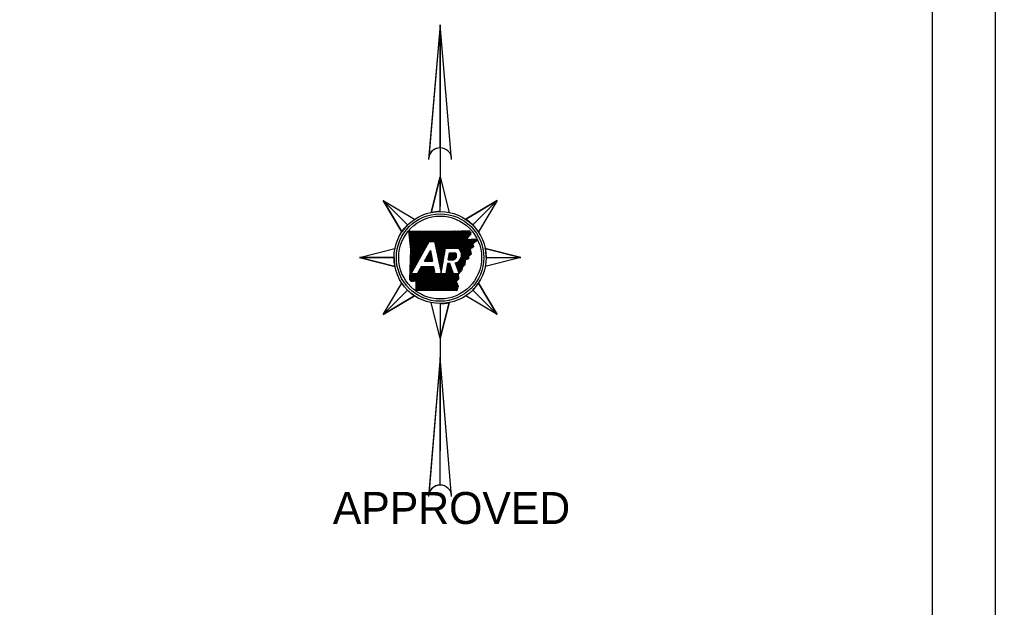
# Model space of a CAD drawing. Extents: x -819161 to 80911, y -6604 to 768454.
# Drawn here: x 48407 to 52278, y 2641 to 4974 of the extents above; entities that cross this region are included whole.
import ezdxf

# ---------------------------------------------------------------- set-up
doc = ezdxf.new("R2010")
doc.units = 0
for name, color, linetype in [('29', 7, 'Continuous'), ('Default', 7, 'Continuous'), ('DSN_DRFT_Common-Annotations', 7, 'Continuous'), ('DSN_DRFT_Junk-No-Plot', 7, 'Continuous'), ('SHET_Border-Lines', 7, 'Continuous')]:
    doc.layers.add(name, color=color, linetype=linetype)

msp = doc.modelspace()

# ---------------------------------------------------------------- linework, layer by layer
at = {"layer": 'Default'}
msp.add_lwpolyline([(35278.1, 10659.9), (35278.1, -340.1), (52278.1, -340.1), (52278.1, 10659.9)], close=True, dxfattribs=at)
at = {"layer": 'DSN_DRFT_Common-Annotations'}
for p, q in [((50075.3, 4953.1), (50030.3, 4426.6)), ((50075.3, 4953.1), (50075.3, 4232)), ((50075.3, 4464.5), (50075.3, 4953.1)), ((50030.9, 4434), (50032.9, 4436)), ((50031.1, 4436.8), (50035.3, 4440.9)), ((50075.3, 4349.1), (50039.7, 4208.6)), ((50075.3, 4212.1), (50075.3, 4349.1)), ((49849.2, 4255.5), (49946.1, 4158.6)), ((49946.1, 4158.6), (49849.2, 4255.5)), ((49849.2, 4255.5), (49923.4, 4131)), ((50301.3, 4255.5), (50176.8, 4181.3)), ((50204.4, 4158.6), (50301.3, 4255.5)), ((50204.4, 4158.6), (50301.3, 4255.5)), ((49950.8, 4132.4), (49952.4, 4134)), ((49951.3, 4127.8), (49957.5, 4134)), ((49951.9, 4123.2), (49962.7, 4134)), ((49952.5, 4118.6), (49967.9, 4134)), ((49953.1, 4114), (49973, 4134)), ((49953.6, 4109.4), (49978.2, 4134)), ((49954.2, 4104.8), (49983.4, 4134)), ((49954.8, 4100.2), (49988.5, 4134)), ((49955.3, 4095.6), (49993.7, 4134)), ((49955.9, 4091.1), (49998.8, 4134)), ((49956.5, 4086.5), (50004, 4134)), ((49957.1, 4081.9), (50009.2, 4134)), ((49957.6, 4077.3), (50014.3, 4134)), ((49958.2, 4072.7), (50019.5, 4134)), ((49958.4, 4021.2), (50071.3, 4134.1)), ((49958.6, 4026.5), (50066.1, 4134.1)), ((49958.7, 4031.9), (50060.9, 4134)), ((49958.8, 4068.1), (50024.7, 4134)), ((49958.9, 4037.2), (50055.7, 4134)), ((49959.1, 4042.6), (50050.5, 4134)), ((49959.3, 4047.9), (50045.4, 4134)), ((49959.3, 4063.5), (50029.8, 4134)), ((49959.4, 4053.2), (50040.2, 4134)), ((49959.6, 4058.6), (50035, 4134)), ((50035.1, 4092.7), (50076.4, 4134.1)), ((50040.3, 4092.7), (50081.6, 4134.1)), ((50045.4, 4092.7), (50086.8, 4134.1)), ((50050.6, 4092.7), (50092.1, 4134.2)), ((50053.8, 4090.8), (50097.3, 4134.3)), ((50054.7, 4086.5), (50102.6, 4134.4)), ((50055.6, 4082.3), (50107.8, 4134.5)), ((50056.5, 4078), (50113.1, 4134.5)), ((50057.5, 4073.8), (50118.3, 4134.6)), ((50058.4, 4069.5), (50123.6, 4134.7)), ((50059.3, 4065.3), (50128.8, 4134.8)), ((50060.2, 4061), (50134.1, 4134.9)), ((50061.1, 4056.7), (50139.3, 4135)), ((50062, 4052.5), (50144.5, 4135)), ((50062.9, 4048.2), (50149.8, 4135.1)), ((50063.8, 4044), (50155, 4135.2)), ((50064.7, 4039.7), (50160.3, 4135.3)), ((50065.6, 4035.5), (50165.6, 4135.4)), ((50101.5, 4066.2), (50170.9, 4135.5)), ((50106.7, 4066.2), (50176.2, 4135.7)), ((50111.9, 4066.2), (50181.5, 4135.8)), ((50117, 4066.2), (50186.7, 4135.9)), ((50122.2, 4066.2), (50192, 4136)), ((50127.4, 4066.2), (50193.2, 4132)), ((50132.5, 4066.2), (50195.7, 4129.3)), ((50137.7, 4066.2), (50196.4, 4124.8)), ((50142.9, 4066.2), (50184.6, 4107.9)), ((49958, 4010.5), (50021.2, 4073.6)), ((49958.2, 4015.8), (50027.9, 4085.6)), ((49959.9, 3965.5), (50032, 4092.7)), ((50032, 4092.7), (50053.4, 4092.7)), ((50096.9, 4066.2), (50146.9, 4066.2)), ((50147.6, 4065.7), (50183.5, 4101.7)), ((50150.4, 4063.4), (50189, 4102)), ((50152.9, 4060.7), (50194.4, 4102.3)), ((50155.1, 4057.8), (50199.9, 4102.5)), ((50157, 4054.5), (50205.3, 4102.8)), ((50158.6, 4051), (50210.8, 4103.1)), ((50159.5, 4031.1), (50206.4, 4078)), ((50159.8, 4047), (50215.7, 4102.8)), ((50160.5, 4042.5), (50218.1, 4100.1)), ((50160.5, 4037.4), (50205.8, 4082.6)), ((50200.6, 4067.1), (50206.9, 4073.4)), ((50215.8, 4092.6), (50220.5, 4097.3)), ((50394.9, 4029.5), (50254.4, 4065)), ((49755.6, 4029.5), (49892.6, 4029.5)), ((49892.6, 4029.5), (49755.6, 4029.5)), ((49755.6, 4029.5), (49896.1, 3993.9)), ((49957.3, 3989.1), (49994.2, 4026)), ((49957.5, 3994.5), (50000.9, 4037.9)), ((49957.7, 3999.8), (50007.7, 4049.8)), ((49957.8, 4005.2), (50014.4, 4061.7)), ((50012.9, 4015.4), (50036.5, 4057.1)), ((50013.2, 4015.4), (50039.7, 4042)), ((50018.3, 4015.4), (50040.6, 4037.7)), ((50019.3, 4026.8), (50038.8, 4046.2)), ((50023.5, 4015.4), (50041.5, 4033.5)), ((50026.1, 4038.7), (50037.9, 4050.5)), ((50028.7, 4015.4), (50042.5, 4029.2)), ((50032.8, 4050.6), (50037, 4054.7)), ((50066.6, 4031.2), (50095.9, 4060.5)), ((50067.5, 4027), (50094.8, 4054.3)), ((50068.4, 4022.7), (50093.7, 4048)), ((50069.3, 4018.4), (50092.6, 4041.8)), ((50070.2, 4014.2), (50091.5, 4035.5)), ((50071.1, 4009.9), (50090.4, 4029.2)), ((50107.8, 4021), (50134.9, 4048.2)), ((50108.8, 4027.3), (50129.8, 4048.2)), ((50109.9, 4033.5), (50124.6, 4048.2)), ((50111, 4039.8), (50119.4, 4048.2)), ((50112.1, 4046), (50114.3, 4048.2)), ((50112.5, 4048.2), (50136, 4048.2)), ((50112.9, 4021), (50137.8, 4045.9)), ((50118.1, 4021), (50139.5, 4042.5)), ((50123.2, 4021), (50140.5, 4038.3)), ((50128.4, 4021), (50140.1, 4032.7)), ((50138.1, 3999.5), (50195.4, 4056.7)), ((50139.5, 3995.7), (50196.4, 4052.5)), ((50140.9, 3991.9), (50197.3, 4048.3)), ((50142.3, 3988.2), (50198.3, 4044.1)), ((50155, 4021.5), (50194.4, 4060.9)), ((50180.7, 4021.3), (50187.9, 4028.6)), ((50257.9, 4029.5), (50394.9, 4029.5)), ((50257.9, 4029.5), (50394.9, 4029.5)), ((49956.8, 3973.1), (49974, 3990.3)), ((49957, 3978.4), (49980.7, 4002.2)), ((49957.1, 3983.8), (49987.4, 4014.1)), ((49957.7, 3937.9), (50012, 3992.2)), ((49960.8, 3935.8), (50017.2, 3992.2)), ((49964.5, 3934.3), (50022.4, 3992.2)), ((49970.6, 3935.3), (50027.5, 3992.2)), ((49975.9, 3935.4), (50032.7, 3992.2)), ((49979.9, 3934.3), (50037.8, 3992.2)), ((49980.1, 3924.1), (50048.2, 3992.2)), ((49980.1, 3929.3), (50043, 3992.2)), ((49980.1, 3919), (50050.9, 3989.7)), ((49999.8, 3992.2), (49984.6, 3965.5)), ((49990.5, 3975.8), (50006.9, 3992.2)), ((49997.2, 3987.7), (50001.7, 3992.2)), ((50050.4, 3992.2), (49999.8, 3992.2)), ((50012.9, 4015.4), (50045.4, 4015.4)), ((50033.8, 4015.4), (50043.4, 4025)), ((50039, 4015.4), (50044.3, 4020.7)), ((50044.2, 4015.4), (50045.2, 4016.4)), ((50072, 4005.7), (50089.3, 4023)), ((50072.9, 4001.4), (50088.2, 4016.7)), ((50073.8, 3997.2), (50087.1, 4010.5)), ((50074.8, 3992.9), (50086.1, 4004.2)), ((50075.7, 3988.7), (50085, 3998)), ((50076.6, 3984.4), (50083.9, 3991.7)), ((50098.9, 3970.6), (50119.3, 3991)), ((50100, 3976.9), (50117.9, 3994.7)), ((50101.1, 3983.1), (50116.5, 3998.5)), ((50102.2, 3989.4), (50115.1, 4002.3)), ((50103.3, 3995.6), (50113.6, 4005.9)), ((50104.4, 4001.9), (50108.4, 4005.9)), ((50113.8, 4005.9), (50105.1, 4005.9)), ((50107.7, 4021), (50129.2, 4021)), ((50128.7, 3965.5), (50113.8, 4005.9)), ((50134.9, 4008.1), (50150.7, 3965.5)), ((50135.3, 4007), (50136.9, 4008.6)), ((50136.7, 4003.2), (50146.6, 4013.1)), ((50143.7, 3984.4), (50174.7, 4015.4)), ((50145.1, 3980.6), (50174.1, 4009.6)), ((50146.5, 3976.8), (50173.5, 4003.9)), ((50147.9, 3973.1), (50163.7, 3988.9)), ((49955.8, 3941.1), (49980.1, 3965.5)), ((49955.9, 3946.4), (49975, 3965.5)), ((49956.1, 3951.7), (49969.8, 3965.5)), ((49956.2, 3957.1), (49964.7, 3965.5)), ((49956.4, 3962.4), (49960.5, 3966.5)), ((49956.6, 3967.8), (49967.2, 3978.4)), ((49984.6, 3965.5), (49959.9, 3965.5)), ((49980.1, 3913.8), (50051.8, 3985.5)), ((49980.2, 3908.7), (50052.7, 3981.2)), ((49980.2, 3903.5), (50053.6, 3977)), ((49980.3, 3898.4), (50054.5, 3972.7)), ((49985.4, 3898.4), (50055.5, 3968.5)), ((49990.6, 3898.4), (50057.6, 3965.5)), ((49995.7, 3898.4), (50062.8, 3965.5)), ((50000.9, 3898.4), (50068, 3965.5)), ((50006, 3898.4), (50073.1, 3965.5)), ((50011.2, 3898.4), (50078.3, 3965.5)), ((50016.4, 3898.4), (50083.5, 3965.5)), ((50021.5, 3898.4), (50088.6, 3965.5)), ((50026.7, 3898.3), (50093.8, 3965.5)), ((50031.8, 3898.3), (50120.7, 3987.2)), ((50037, 3898.3), (50122.1, 3983.4)), ((50042.2, 3898.3), (50123.5, 3979.6)), ((50047.3, 3898.3), (50124.9, 3975.9)), ((50052.5, 3898.3), (50126.3, 3972.1)), ((50098, 3965.5), (50056.1, 3965.5)), ((50057.6, 3898.3), (50127.7, 3968.3)), ((50062.8, 3898.3), (50130, 3965.5)), ((50067.9, 3898.3), (50135.1, 3965.5)), ((50073.1, 3898.3), (50140.3, 3965.5)), ((50077.5, 3980.1), (50082.8, 3985.5)), ((50078.3, 3898.3), (50145.5, 3965.5)), ((50078.4, 3975.9), (50081.7, 3979.2)), ((50079.3, 3971.6), (50080.6, 3972.9)), ((50083.4, 3898.3), (50147.2, 3962)), ((50088.6, 3898.2), (50147.4, 3957.1)), ((50093.7, 3898.2), (50147.7, 3952.2)), ((50150.7, 3965.5), (50128.7, 3965.5)), ((50149.3, 3969.3), (50161.5, 3981.5)), ((50098.9, 3898.2), (50147.9, 3947.2)), ((50104, 3898.2), (50139.4, 3933.6)), ((50109.2, 3898.2), (50141, 3930)), ((50114.4, 3898.2), (50142.6, 3926.4)), ((50119.5, 3898.2), (50144.2, 3922.9)), ((50124.7, 3898.2), (50145.8, 3919.3)), ((50129.8, 3898.2), (50147.1, 3915.5)), ((50301.3, 3803.4), (50227.1, 3927.9)), ((49849.2, 3803.4), (49946.1, 3900.3)), ((49946.1, 3900.3), (49849.2, 3803.4)), ((49849.2, 3803.4), (49973.7, 3877.6)), ((50135, 3898.2), (50144.8, 3908)), ((50140.1, 3898.2), (50142.4, 3900.5)), ((50204.4, 3900.3), (50301.3, 3803.4)), ((50204.4, 3900.3), (50301.3, 3803.4)), ((50075.3, 3709.8), (50110.8, 3850.3)), ((50075.3, 3846.8), (50075.3, 3846.8)), ((50075.3, 3846.8), (50075.3, 3262.1)), ((50075.3, 3846.8), (50075.3, 3709.8)), ((50075.3, 3633.5), (50030.2, 3088.5)), ((50075.3, 3126.6), (50075.3, 3633.5))]:
    msp.add_line(p, q, dxfattribs=at)
for points in [[(50120.9, 4418.9), (50075.3, 4953.1), (50029.6, 4418.9)], [(50039.7, 4208.6), (50075.3, 4349.1), (50110.8, 4208.6)], [(49923.4, 4131), (49849.2, 4255.5), (49973.7, 4181.3)], [(50176.8, 4181.3), (50301.3, 4255.5), (50227.1, 4131)], [(49950.6, 4134), (50021.8, 4134), (50084.4, 4134.1), (50158.2, 4135.2), (50192.4, 4136)], [(49955.7, 3941.2), (49959.7, 4060.8), (49950.6, 4134)], [(49896.1, 3993.9), (49755.6, 4029.5), (49896.1, 4065)], [(50053.4, 4092.7), (50079.9, 3968.9), (50096.9, 4066.2)], [(50214.8, 4103.3), (50220.9, 4096.8), (50205.5, 4084.2), (50207.2, 4071.4), (50194, 4062.8), (50198.5, 4043.1), (50188.4, 4033.9), (50187.5, 4023.8), (50175.1, 4019.3), (50173.2, 4000.3), (50164.3, 3990.8), (50160, 3976.5), (50147.1, 3964.6), (50148.1, 3943.7), (50139.3, 3933.9), (50147.3, 3916), (50141.7, 3898.2)], [(50181.8, 4101.6), (50215.2, 4103.3)], [(50254.4, 4065), (50394.9, 4029.5), (50254.4, 3993.9)], [(50036.5, 4057.1), (50045.4, 4015.4)], [(50107.7, 4021), (50112.5, 4048.2)], [(50056.1, 3965.5), (50050.4, 3992.2)], [(50105.1, 4005.9), (50098, 3965.5)], [(49973.7, 3877.6), (49849.2, 3803.4), (49923.4, 3927.9)], [(50141.7, 3898.2), (49980.2, 3898.4), (49980.1, 3934.1)], [(50227.1, 3927.9), (50301.3, 3803.4), (50176.8, 3877.6)], [(50110.8, 3850.3), (50075.3, 3709.8), (50039.7, 3850.3)], [(50120.9, 3081), (50075.3, 3633.5), (50029.6, 3081)]]:
    msp.add_lwpolyline(points, dxfattribs=at)
for radius in [182.6, 173.5, 164.4]:
    msp.add_circle((50075.3, 4029.5), radius, dxfattribs=at)
for centre, radius, start, end in [((50075.3, 4418.9), 45.7, 0, 180), ((50075.3, 4418.9), 45.7, 90, 170.2296), ((50075.3, 4029.5), 182.6, 90, 101.2291), ((50075.3, 4029.5), 182.6, 45, 56.2291), ((50075.3, 4029.5), 182.6, 135, 146.2291), ((50128.3, 4039.7), 32.3, 281.8626, 54.8705), ((50075.3, 4029.5), 182.6, 0, 11.2291), ((50075.3, 4029.5), 182.6, 180, 191.2291), ((50124, 4036.8), 16.5, 288.1268, 43.8902), ((50075.3, 4029.5), 182.6, 315, 326.2291), ((50075.3, 4029.5), 182.6, 225, 236.2291), ((50075.3, 4029.5), 182.6, 270, 281.2291), ((50075.3, 3081), 45.7, 0, 180), ((50075.3, 3081), 45.7, 90, 170.5511)]:
    msp.add_arc(centre, radius, start, end, dxfattribs=at)
for points in [[(50192.4, 4136), (50192.6, 4134.1), (50193.2, 4133.1), (50193.3, 4131.2), (50194, 4130.4), (50195.3, 4129.6), (50196.5, 4128.4), (50196.7, 4126.9), (50196.4, 4125.3), (50196.3, 4123.6), (50196.1, 4122.1), (50195.9, 4120.7), (50194.8, 4119.6), (50193.8, 4118.8), (50192.9, 4117.9), (50192.2, 4117), (50191, 4115.9), (50189.9, 4114.8), (50189, 4113.8), (50188, 4112.6), (50187.6, 4111.2), (50186.6, 4110.3), (50185.8, 4109.4), (50184.7, 4108.2), (50184.2, 4107), (50183.2, 4105.6), (50183, 4104.3), (50182.3, 4103.2), (50182.3, 4103.1)], [(49980.1, 3934.1), (49980.3, 3934), (49979.4, 3934.6), (49978.3, 3935.1), (49977, 3935.2), (49975.4, 3935.4), (49974, 3935.6), (49972.6, 3936.5), (49971.1, 3935.5), (49969.4, 3934.8), (49968.5, 3935.6), (49967.2, 3935.1), (49966.3, 3935.4), (49964.8, 3934.3), (49963.3, 3934.7), (49962.2, 3934.4), (49960.9, 3934.4), (49960.7, 3935.9), (49959.4, 3936.2), (49958.3, 3936.8), (49957.5, 3938.3), (49957, 3939.5), (49955.7, 3941.2)]]:
    msp.add_spline(points, degree=3, dxfattribs=at)
at = {"layer": 'DSN_DRFT_Junk-No-Plot'}
msp.add_lwpolyline([(35278.1, -340.1), (52278.1, -340.1), (52278.1, 10659.9), (35278.1, 10659.9)], close=True, dxfattribs=at)
at = {"layer": 'SHET_Border-Lines'}
msp.add_lwpolyline([(35528.1, -90.1), (52028.1, -90.1), (52028.1, 10409.9), (35528.1, 10409.9)], close=True, dxfattribs=at)
msp.add_lwpolyline([(35528.1, -90.1), (52028.1, -90.1), (52028.1, 10409.9), (35528.1, 10409.9)], close=True, dxfattribs=at)

# ---------------------------------------------------------------- texts
at = {"layer": '29'}
msp.add_text('APPROVED', height=126.7, dxfattribs=at).set_placement((49649.7, 2972.5))
at = {"layer": 'DSN_DRFT_Common-Annotations'}
msp.add_text('DWB 7-27-17', height=3.552, dxfattribs=at).set_placement((50064.1, 3862))

doc.saveas('drawing.dxf')
